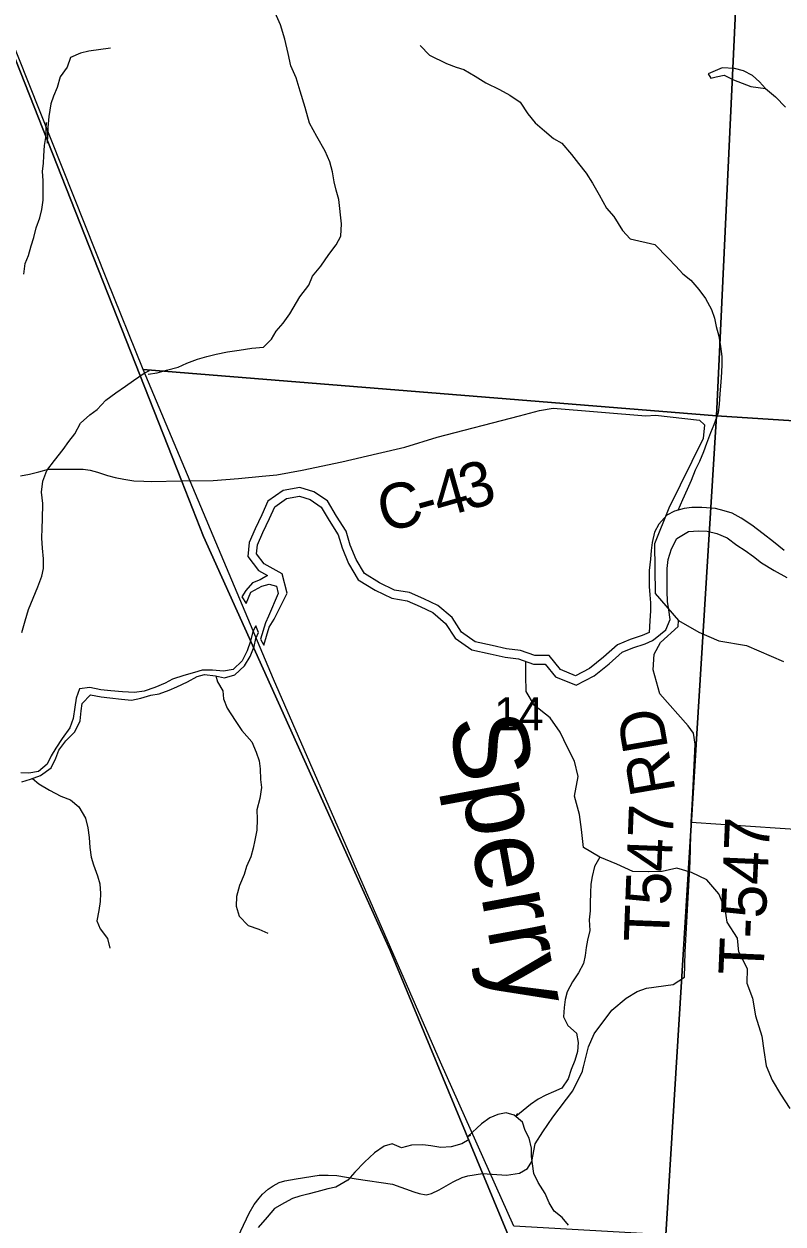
# Model space of a CAD drawing. Extents: x 0 to 34, y 0 to 22.
# Drawn here: x 3.511 to 4.467, y 16.547 to 18.059 of the extents above; entities that cross this region are included whole.
import ezdxf

# ---------------------------------------------------------------- set-up
doc = ezdxf.new("R2010")
doc.units = 0
for name, color, linetype in [('GM_X_County_Road', 7, 'Continuous'), ('GM_X_County_Road_Text', 7, 'Continuous'), ('GM_X_Minor_Lake', 7, 'Continuous'), ('GM_X_Minor_River', 7, 'Continuous'), ('GM_X_Minor_River_Text', 7, 'Continuous'), ('GM_X_Section', 7, 'Continuous'), ('GM_X_Section_Text', 7, 'Continuous'), ('GM_X_Township_Road', 7, 'Continuous'), ('GM_X_Township_Road_Text', 7, 'Continuous'), ('GM_X_Unincorporated', 7, 'Continuous'), ('SH_Cut_Line', 7, 'Continuous')]:
    doc.layers.add(name, color=color, linetype=linetype)

msp = doc.modelspace()

# ---------------------------------------------------------------- linework, layer by layer
at = {"layer": 'GM_X_County_Road'}
msp.add_lwpolyline([(3.7092, 17.4834), (3.7489, 17.4839), (3.7808, 17.4867), (3.8108, 17.4895), (3.8293, 17.4912), (3.8612, 17.497), (3.9113, 17.5076), (3.9562, 17.5182), (3.9907, 17.5259), (4.0314, 17.5388), (4.1351, 17.5653), (4.1602, 17.5723), (4.1772, 17.5752), (4.2943, 17.5655), (4.3062, 17.5662), (4.3616, 17.5601), (4.368, 17.5541), (4.3665, 17.537), (4.3229, 17.449), (4.3051, 17.4042), (4.3059, 17.3416), (4.3354, 17.3075), (4.3608, 17.293), (4.3859, 17.282), (4.4211, 17.2763), (4.4677, 17.2559)], dxfattribs=at)
at = {"layer": 'GM_X_Minor_Lake'}
for points in [[(4.445, 17.9779), (4.4375, 17.9864), (4.4284, 17.9945), (4.4171, 18.0002), (4.4058, 18.003), (4.3903, 18.0042), (4.3728, 17.9964)], [(4.3728, 17.9964), (4.3762, 17.991), (4.3826, 17.9925), (4.3928, 17.9947), (4.4045, 17.9889), (4.4265, 17.9804), (4.445, 17.9779)]]:
    msp.add_lwpolyline(points, dxfattribs=at)
at = {"layer": 'GM_X_Minor_River'}
for p, q in [((3.7852, 17.3373), (3.7906, 17.3289)), ((3.8061, 17.2925), (3.8027, 17.3008)), ((3.8088, 17.284), (3.8128, 17.2764))]:
    msp.add_line(p, q, dxfattribs=at)
for points in [[(3.6671, 17.6178), (3.6784, 17.6198), (3.6902, 17.6229), (3.7049, 17.6269), (3.7159, 17.6319), (3.7291, 17.637), (3.7409, 17.6401), (3.753, 17.6433), (3.767, 17.6461), (3.7818, 17.6481), (3.7977, 17.6509), (3.8125, 17.6522), (3.8226, 17.6622), (3.8286, 17.6721), (3.8372, 17.6824), (3.8458, 17.6939), (3.8581, 17.7153), (3.8694, 17.7302), (3.8742, 17.7416), (3.8847, 17.7539), (3.8948, 17.7688), (3.9042, 17.781), (3.9098, 17.7917), (3.9108, 17.8073), (3.9074, 17.838), (3.9039, 17.8497), (3.9015, 17.8603), (3.8995, 17.8728), (3.8959, 17.8857), (3.8901, 17.8989), (3.8797, 17.9174), (3.8704, 17.9341), (3.8649, 17.9541), (3.8586, 17.9746), (3.8535, 17.9912), (3.8469, 18.0067), (3.8437, 18.0222), (3.8394, 18.04), (3.8339, 18.0582), (3.8273, 18.0733)], [(3.6197, 18.0288), (3.5924, 18.0252), (3.5818, 18.0224), (3.5694, 18.017), (3.5653, 18.0048), (3.5563, 17.9925), (3.5523, 17.9792), (3.5478, 17.9685), (3.5445, 17.9586), (3.542, 17.9427), (3.5406, 17.929), (3.5404, 17.9184), (3.5401, 17.9089)], [(4.0099, 18.0322), (4.0217, 18.0198), (4.0431, 18.0094), (4.0553, 18.0049), (4.0648, 18.002), (4.0793, 17.9934), (4.0927, 17.9851), (4.1099, 17.9766), (4.1228, 17.9695), (4.1358, 17.9609), (4.1455, 17.9462), (4.1547, 17.9345), (4.1665, 17.9244), (4.178, 17.915), (4.1883, 17.909), (4.2006, 17.8947), (4.2091, 17.8834), (4.2191, 17.8713), (4.2268, 17.8585), (4.2353, 17.8438), (4.2446, 17.8272), (4.2538, 17.8166), (4.2646, 17.7989), (4.2745, 17.7884)], [(4.445, 17.9779), (4.4575, 17.9675), (4.4699, 17.9545)], [(3.5105, 17.744), (3.5121, 17.7576), (3.5163, 17.7674), (3.5198, 17.7795), (3.5229, 17.7901), (3.5261, 17.8022), (3.5307, 17.8151), (3.5331, 17.8253), (3.5347, 17.8374), (3.5349, 17.8621), (3.5342, 17.8734), (3.5354, 17.8837), (3.5355, 17.8932), (3.5367, 17.906), (3.5387, 17.9189), (3.5386, 17.9276), (3.5391, 17.935)], [(4.2745, 17.7884), (4.3056, 17.7813), (4.3223, 17.764), (4.3321, 17.7541), (4.3408, 17.7445), (4.351, 17.7365), (4.3608, 17.7246), (4.3691, 17.7135), (4.377, 17.6994), (4.3807, 17.6884), (4.3829, 17.6781), (4.3859, 17.6659), (4.3884, 17.653), (4.3899, 17.6404), (4.3898, 17.6302), (4.3894, 17.6207), (4.3885, 17.6081), (4.3873, 17.5933), (4.3864, 17.5804), (4.3852, 17.5694), (4.3798, 17.5542), (4.3755, 17.544), (4.3705, 17.5307), (4.3666, 17.5201), (4.3616, 17.508), (4.3562, 17.497), (4.3512, 17.4841), (4.3462, 17.4728), (4.3404, 17.4595), (4.3343, 17.4464)], [(3.508, 17.2924), (3.5123, 17.3072), (3.5162, 17.3215), (3.5224, 17.3359), (3.5282, 17.3499), (3.5332, 17.3635), (3.5352, 17.3733), (3.5353, 17.3855), (3.5339, 17.3987), (3.5332, 17.4113), (3.5337, 17.4238), (3.5342, 17.4355), (3.5343, 17.4549), (3.5329, 17.4693), (3.5345, 17.4833), (3.5396, 17.4965), (3.5491, 17.5093), (3.5602, 17.5229), (3.5671, 17.5331), (3.5747, 17.5429), (3.582, 17.5561), (3.5935, 17.5666), (3.603, 17.5734), (3.6137, 17.5854), (3.6263, 17.5944), (3.6388, 17.603), (3.6487, 17.6102), (3.662, 17.6192), (3.6689, 17.6228)], [(4.2984, 17.2923), (4.2893, 17.2885), (4.2742, 17.2835), (4.2583, 17.2771), (4.2407, 17.2613), (4.2232, 17.247), (4.2057, 17.238), (4.1868, 17.2457), (4.1725, 17.2633), (4.1543, 17.2634), (4.1362, 17.2696), (4.1187, 17.2721), (4.1006, 17.276), (4.0793, 17.2807), (4.062, 17.293), (4.05, 17.3113), (4.0319, 17.3266), (4.0145, 17.3351), (3.9963, 17.3428), (3.9774, 17.346), (3.9585, 17.3552), (3.9396, 17.3667), (3.9291, 17.3843), (3.9216, 17.4026), (3.9164, 17.4201), (3.9044, 17.4391), (3.8931, 17.4582), (3.8757, 17.4697), (3.8583, 17.4752), (3.8371, 17.4715), (3.818, 17.458), (3.8104, 17.4406), (3.8019, 17.4232), (3.7942, 17.4058), (3.7926, 17.3883), (3.8062, 17.3708), (3.8176, 17.3643)], [(3.8128, 17.2764), (3.8195, 17.2992), (3.8257, 17.3094), (3.8421, 17.342), (3.8359, 17.3663), (3.8134, 17.3791), (3.8038, 17.3915), (3.8048, 17.403), (3.8117, 17.4186), (3.8202, 17.436), (3.8267, 17.4509), (3.8413, 17.4613), (3.8576, 17.4641), (3.8711, 17.4599), (3.8851, 17.4506), (3.8952, 17.4335), (3.9065, 17.4156), (3.9114, 17.399), (3.9194, 17.3794), (3.9317, 17.3589), (3.9533, 17.3457), (3.974, 17.3356), (3.9933, 17.3324), (4.01, 17.3252), (4.0259, 17.3175), (4.0418, 17.304), (4.0541, 17.2853), (4.0749, 17.2706), (4.0982, 17.2654), (4.1168, 17.2614), (4.1336, 17.2591), (4.1525, 17.2527), (4.1673, 17.2525), (4.1802, 17.2368), (4.2062, 17.2261), (4.2292, 17.2379), (4.2478, 17.2531), (4.2641, 17.2678), (4.2779, 17.2733), (4.2931, 17.2784), (4.3026, 17.2824)], [(4.4682, 17.3958), (4.4549, 17.4068), (4.442, 17.4167), (4.4275, 17.4277), (4.4142, 17.4365), (4.4028, 17.443), (4.393, 17.446), (4.3819, 17.4487), (4.3648, 17.4502), (4.3519, 17.4498), (4.3424, 17.4487), (4.3303, 17.4453), (4.3204, 17.4404), (4.3105, 17.429), (4.3051, 17.4187), (4.3021, 17.4058), (4.301, 17.3959), (4.2998, 17.3849), (4.2983, 17.3708), (4.2983, 17.3503), (4.299, 17.34), (4.2998, 17.3298), (4.2998, 17.3199), (4.299, 17.3073), (4.2984, 17.2923)], [(4.3026, 17.2824), (4.3058, 17.2848), (4.3195, 17.2958), (4.3248, 17.3087), (4.3233, 17.3209), (4.3214, 17.3315), (4.321, 17.3445), (4.321, 17.373), (4.3222, 17.3844), (4.3264, 17.3977), (4.3332, 17.411), (4.348, 17.4197), (4.3606, 17.4208), (4.3716, 17.4201), (4.3834, 17.4174), (4.3967, 17.4117), (4.4088, 17.4025), (4.4191, 17.3957), (4.4297, 17.3881), (4.44, 17.3801), (4.456, 17.3706), (4.4719, 17.3618)], [(3.8176, 17.3643), (3.8081, 17.3587), (3.7986, 17.355), (3.7903, 17.3452), (3.7852, 17.3373)], [(3.7906, 17.3289), (3.7967, 17.3434), (3.8102, 17.3508), (3.8196, 17.3535), (3.8287, 17.3507)], [(3.8287, 17.3507), (3.831, 17.3417), (3.8189, 17.3132), (3.815, 17.3045), (3.8088, 17.284)], [(3.8027, 17.3008), (3.7991, 17.2939), (3.796, 17.2814), (3.7917, 17.2693), (3.7856, 17.2569), (3.7742, 17.2459), (3.762, 17.2438), (3.7484, 17.245), (3.7352, 17.2451), (3.7257, 17.2422), (3.712, 17.2385), (3.698, 17.2337), (3.6885, 17.2288), (3.6756, 17.2232), (3.6623, 17.2184), (3.6498, 17.217), (3.635, 17.2178), (3.6203, 17.2191), (3.6074, 17.2203), (3.5938, 17.2231), (3.5805, 17.2217), (3.5763, 17.2096), (3.5747, 17.1986), (3.5727, 17.1842), (3.5684, 17.1725), (3.5588, 17.1589), (3.5508, 17.1469), (3.545, 17.137), (3.54, 17.1265), (3.529, 17.1174), (3.5169, 17.1153), (3.5066, 17.1157)], [(3.5081, 17.1043), (3.5187, 17.1077), (3.5316, 17.1121), (3.5449, 17.1219), (3.5507, 17.1343), (3.5546, 17.1442), (3.5634, 17.1559), (3.5748, 17.1675), (3.5814, 17.1811), (3.5826, 17.1936), (3.5838, 17.2031), (3.5945, 17.214), (3.6081, 17.2116), (3.6187, 17.21), (3.6334, 17.2084), (3.6463, 17.2071), (3.658, 17.2097), (3.6706, 17.2134), (3.6812, 17.2152), (3.6937, 17.22), (3.7032, 17.2241), (3.7169, 17.2305), (3.7287, 17.2372), (3.7381, 17.2394), (3.7521, 17.2378), (3.7635, 17.2354), (3.7764, 17.2391), (3.7886, 17.2504), (3.7955, 17.2621), (3.8005, 17.2749), (3.8028, 17.2848), (3.8061, 17.2925)], [(4.2971, 16.9908), (4.2778, 16.9915), (4.2574, 17.0007), (4.2362, 17.0093), (4.2158, 17.0215), (4.2129, 17.0443), (4.2107, 17.0633), (4.2041, 17.0862), (4.2088, 17.1112), (4.2043, 17.1302), (4.1953, 17.1477), (4.1863, 17.1668), (4.1736, 17.1851), (4.1539, 17.2004), (4.1434, 17.218), (4.1428, 17.2385), (4.1429, 17.2559), (4.1429, 17.2554)], [(3.7523, 17.2378), (3.7547, 17.2302), (3.7611, 17.2191), (3.7621, 17.2089), (3.7666, 17.1971), (3.7767, 17.1815), (3.7853, 17.1689), (3.7977, 17.1548), (3.8032, 17.1415), (3.8069, 17.1308), (3.8084, 17.1206), (3.8086, 17.1073), (3.8101, 17.097), (3.8077, 17.0834), (3.8042, 17.069), (3.8045, 17.0573), (3.804, 17.0436), (3.8016, 17.0308), (3.7996, 17.0209), (3.7965, 17.0099), (3.7911, 16.9978), (3.788, 16.9876), (3.7822, 16.9737), (3.7783, 16.9597), (3.7782, 16.9475), (3.7819, 16.935), (3.7932, 16.9235), (3.8064, 16.9185), (3.8177, 16.9135)], [(3.5214, 17.1086), (3.5296, 17.1019), (3.5428, 17.0938), (3.5571, 17.0861), (3.5692, 17.0815), (3.5797, 17.0727), (3.588, 17.0586), (3.5913, 17.0464), (3.5927, 17.0343), (3.5937, 17.0214), (3.5955, 17.0096), (3.5981, 16.9997), (3.6033, 16.9857), (3.6062, 16.9758), (3.6073, 16.9637), (3.6068, 16.9534), (3.6048, 16.9424), (3.6025, 16.9292), (3.6065, 16.9193), (3.6159, 16.9067), (3.6188, 16.8946)], [(4.2362, 17.0093), (4.2295, 16.9975), (4.2264, 16.985), (4.2248, 16.9755), (4.2244, 16.9645), (4.2239, 16.9513), (4.2239, 16.9418), (4.2227, 16.9304), (4.2234, 16.9171), (4.2207, 16.905), (4.2191, 16.8955), (4.2179, 16.8853), (4.2156, 16.8754), (4.2095, 16.8637), (4.2019, 16.8524), (4.195, 16.8399), (4.1923, 16.83), (4.1911, 16.8198), (4.1903, 16.8081), (4.1959, 16.7974), (4.2068, 16.7875), (4.2087, 16.7757), (4.2082, 16.7644), (4.2048, 16.753), (4.2002, 16.742), (4.1963, 16.7299), (4.1883, 16.7182), (4.1777, 16.7137), (4.1682, 16.7096), (4.1584, 16.7043), (4.1489, 16.6979), (4.1305, 16.6825), (4.133, 16.6862)], [(4.4113, 16.8898), (4.4096, 16.9075), (4.3968, 16.9273), (4.3939, 16.9444), (4.386, 16.9634), (4.371, 16.9809), (4.3517, 16.9902), (4.3332, 16.9956), (4.3146, 16.9915), (4.2971, 16.9908), (4.2975, 16.9912)], [(4.4113, 16.8898), (4.4216, 16.869), (4.4212, 16.8507), (4.4287, 16.8317), (4.4324, 16.8096), (4.4403, 16.7838), (4.4426, 16.7659), (4.4459, 16.7465), (4.4531, 16.7286), (4.4636, 16.7107), (4.4757, 16.6925)], [(4.1969, 16.5456), (4.1886, 16.5555), (4.1785, 16.5635), (4.1725, 16.5738), (4.1672, 16.5855), (4.1586, 16.5996), (4.153, 16.6106), (4.1501, 16.6323), (4.1501, 16.6429), (4.1472, 16.6554), (4.1423, 16.6649), (4.1386, 16.6756), (4.1284, 16.6843), (4.1182, 16.6871), (4.1076, 16.6852), (4.0974, 16.6811), (4.0871, 16.6732), (4.0699, 16.6573), (4.0738, 16.6592)], [(4.0715, 16.6536), (4.0622, 16.6481), (4.0489, 16.6444), (4.0357, 16.6437), (4.0232, 16.6457), (4.013, 16.6469), (3.999, 16.6466), (3.9862, 16.6433), (3.9745, 16.6483), (3.9646, 16.6453), (3.9521, 16.6367), (3.9395, 16.625), (3.9274, 16.6125), (3.9186, 16.6024), (3.9034, 16.5937), (3.8936, 16.5915), (3.8796, 16.5878), (3.8682, 16.5848), (3.8584, 16.5822), (3.8489, 16.5793), (3.839, 16.574), (3.8261, 16.5665), (3.817, 16.5559), (3.8059, 16.5427)]]:
    msp.add_lwpolyline(points, dxfattribs=at)
at = {"layer": 'GM_X_Section'}
for points in [[(3.4282, 18.6383), (4.4314, 18.5943), (4.383, 17.5655), (3.6608, 17.6237), (3.615, 17.7371), (3.4191, 18.2301), (3.4042, 18.2698)], [(4.4314, 18.5943), (5.4469, 18.529), (5.3838, 17.5009), (4.383, 17.5655)], [(3.6608, 17.6237), (4.383, 17.5655), (4.3194, 16.5337), (4.128, 16.5445), (4.0354, 16.7509), (3.8249, 17.2336)], [(4.383, 17.5655), (5.3838, 17.5009), (5.3178, 16.4777), (4.3194, 16.5337)]]:
    msp.add_lwpolyline(points, close=True, dxfattribs=at)
at = {"layer": 'GM_X_Township_Road'}
msp.add_line((4.3514, 17.0533), (4.7239, 17.0284), dxfattribs=at)
for points in [[(3.5065, 17.4901), (3.5176, 17.4918), (3.5293, 17.4951), (3.5414, 17.4983), (3.5561, 17.4985), (3.572, 17.4985), (3.5852, 17.4983), (3.594, 17.497), (3.6034, 17.4945), (3.6158, 17.4905), (3.6256, 17.4878), (3.6363, 17.4855), (3.6493, 17.4838), (3.6616, 17.483), (3.6711, 17.4826), (3.7092, 17.4834)], [(4.3533, 17.0903), (4.3563, 17.1519), (4.354, 17.1656), (4.3476, 17.175), (4.3116, 17.2153), (4.3032, 17.2456), (4.3048, 17.265), (4.3127, 17.2798), (4.3347, 17.3002), (4.3354, 17.3075)], [(4.2153, 16.7438), (4.2157, 16.7454), (4.222, 16.7703), (4.2289, 16.7866), (4.2513, 16.8166), (4.2692, 16.8317), (4.2833, 16.84), (4.295, 16.8445), (4.3287, 16.849), (4.3429, 16.8583), (4.3437, 16.8897), (4.3501, 17.004), (4.3514, 17.0533), (4.3533, 17.0903)], [(4.0885, 16.6108), (4.1185, 16.6088), (4.1348, 16.6114), (4.145, 16.6171), (4.1507, 16.6258), (4.1546, 16.6482), (4.1645, 16.6633), (4.177, 16.6819), (4.2021, 16.7149), (4.2144, 16.7399), (4.2153, 16.7438)], [(3.7699, 16.5092), (3.7946, 16.5607), (3.8009, 16.5716), (3.8071, 16.5799), (3.8113, 16.5848), (3.8185, 16.5912), (3.8245, 16.5954), (3.8323, 16.5994), (3.8394, 16.6017), (3.8536, 16.6042), (3.8827, 16.6086), (3.894, 16.6088), (3.9049, 16.6082), (3.929, 16.604), (3.9749, 16.5973), (4.0017, 16.5875), (4.0086, 16.5854), (4.0172, 16.5841), (4.0239, 16.5854), (4.0337, 16.5902), (4.0513, 16.6002), (4.0628, 16.6059), (4.0697, 16.6078), (4.0885, 16.6108)]]:
    msp.add_lwpolyline(points, dxfattribs=at)
at = {"layer": 'GM_X_Unincorporated'}
msp.add_lwpolyline([(2.2853, 20.9), (2.1, 20.9), (2.1, 14.1), (2.8399, 14.1), (2.9778, 14.1609), (3.8099, 14.5285), (4.2904, 14.7408), (4.3998, 14.7897), (4.802, 14.9692), (4.4847, 15.685), (4.2937, 16.1161), (4.0882, 16.6114), (3.972, 16.8916), (3.7367, 17.4136), (3.709, 17.484), (3.4011, 18.2653), (3.1249, 18.9173), (3.0781, 19.0279), (2.9956, 19.2227), (2.9553, 19.318), (2.7473, 19.8121), (2.418, 20.5866)], close=True, dxfattribs=at)
msp.add_lwpolyline([(3.4011, 18.2653), (3.709, 17.484), (3.7367, 17.4136), (3.972, 16.8916), (4.0882, 16.6114), (4.2937, 16.1161)], dxfattribs=at)
at = {"layer": 'SH_Cut_Line'}
for points in [[(4.2937, 16.1161), (4.0882, 16.6114), (3.972, 16.8916), (3.7367, 17.4136), (3.709, 17.484), (3.4011, 18.2653), (3.4595, 19.1305), (3.4599, 19.1361), (3.5099, 19.8769), (3.5456, 20.4047), (3.5457, 20.4056), (3.5462, 20.4144), (3.5651, 20.6937), (3.8602, 20.6728), (4.3099, 20.6409), (6.6484, 20.4847), (6.6568, 20.5136), (6.769, 20.9), (2.1, 20.9), (2.1, 14.1)], [(8.9, 14.1), (8.9, 20.9), (6.769, 20.9), (6.6568, 20.5136), (6.6484, 20.4847), (4.3099, 20.6409), (3.8602, 20.6728), (3.5651, 20.6937), (3.5462, 20.4144), (3.5457, 20.4056), (3.5456, 20.4047), (3.5099, 19.8769), (3.4599, 19.1361), (3.4595, 19.1305), (3.4011, 18.2653), (3.709, 17.484), (3.7367, 17.4136), (3.972, 16.8916), (4.0882, 16.6114), (4.2937, 16.1161)]]:
    msp.add_lwpolyline(points, dxfattribs=at)

# ---------------------------------------------------------------- texts
at = {"layer": 'GM_X_County_Road_Text'}
for s, rotation, p in [('4', 15.8275, (4.0344, 17.4362)), ('3', 15.9617, (4.0682, 17.4458)), ('C', 13.065, (3.9635, 17.4187)), ('-', 15.449, (4.0115, 17.4299))]:
    msp.add_text(s, height=0.0568, rotation=rotation, dxfattribs=at).set_placement(p)
at = {"layer": 'GM_X_Minor_River_Text'}
msp.add_text('Sperry', height=0.09468, rotation=280.4936, dxfattribs=at).set_placement((4.0454, 17.1822))
at = {"layer": 'GM_X_Section_Text'}
msp.add_text('14', height=0.04186, rotation=0, dxfattribs=at).set_placement((4.1029, 17.1691))
at = {"layer": 'GM_X_Township_Road_Text'}
for s, rotation, p in [('RD', 99.7986, (4.3318, 17.0924)), ('T547', 87.7828, (4.3231, 16.9016)), ('T-547', 87.4786, (4.4422, 16.8599))]:
    msp.add_text(s, height=0.05682, rotation=rotation, dxfattribs=at).set_placement(p)

doc.saveas('drawing.dxf')
